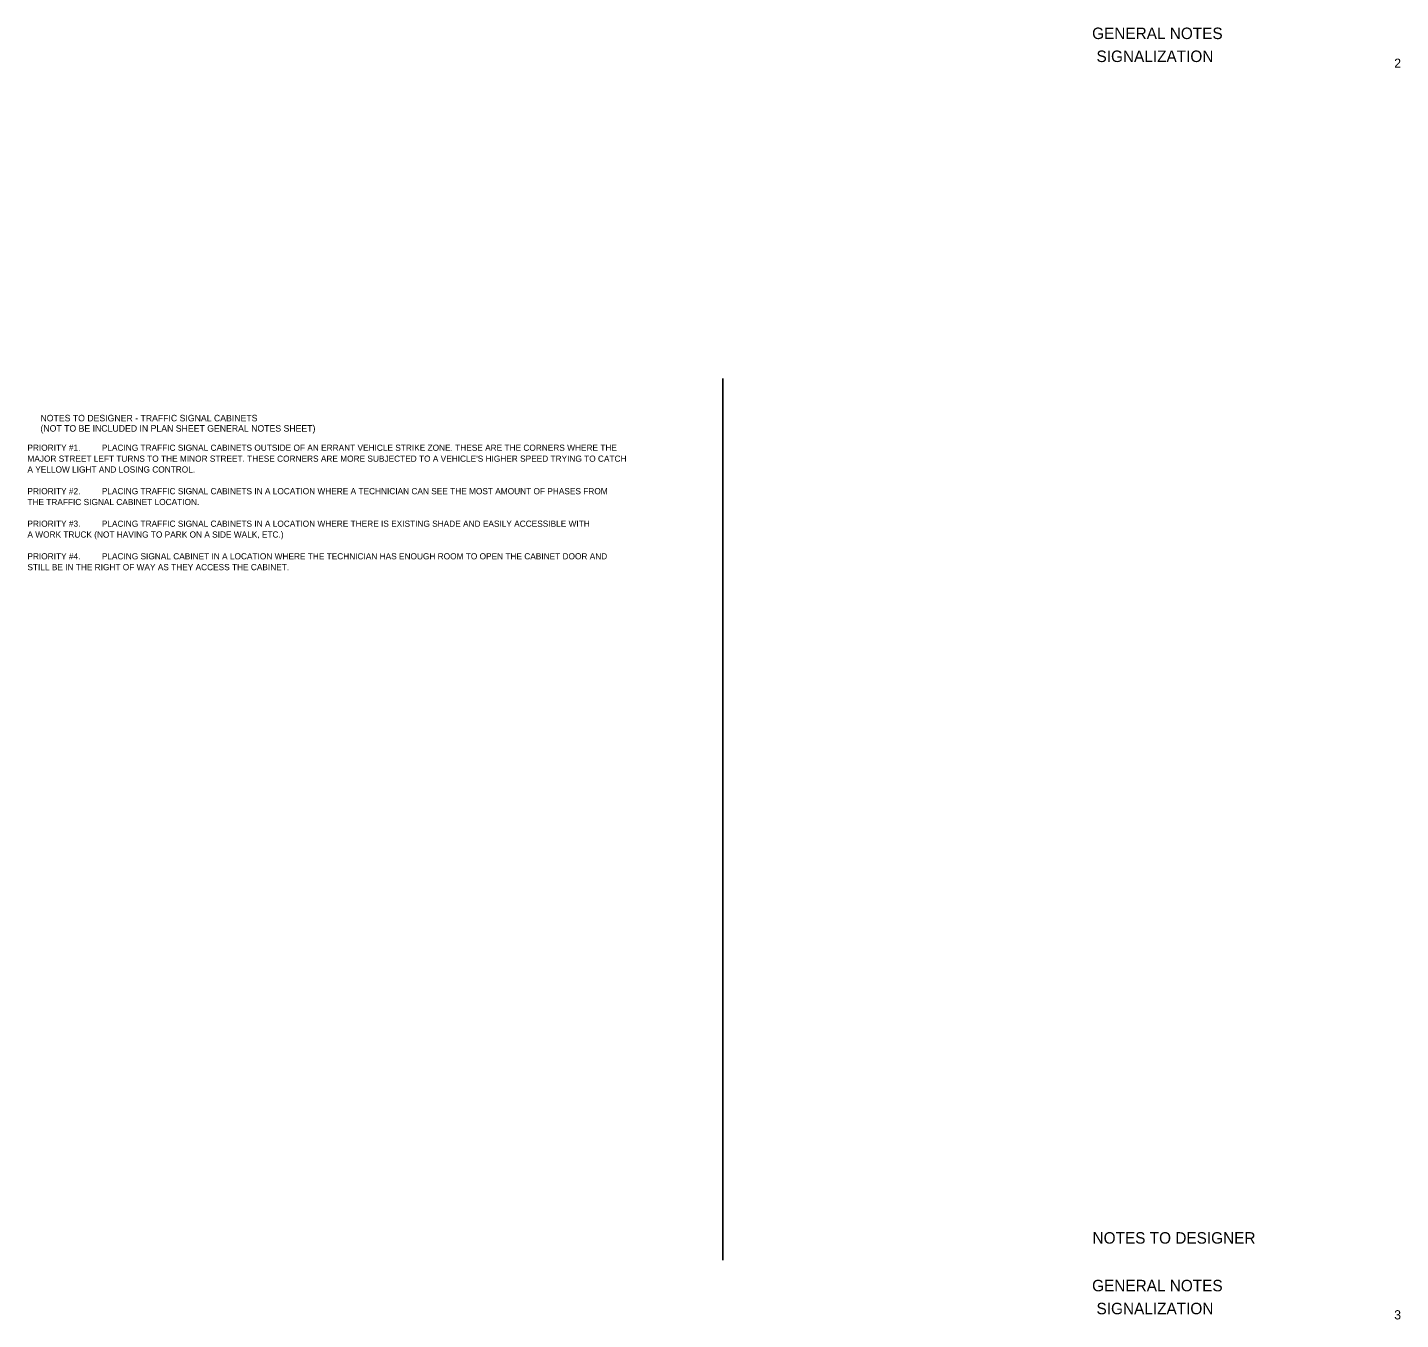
# Model space of a CAD drawing. Extents: x 2479946 to 2483081, y 3677527 to 3681234.
# Drawn here: x 2480014 to 2481509, y 3677527 to 3678934 of the extents above; entities that cross this region are included whole.
import ezdxf

# ---------------------------------------------------------------- set-up
doc = ezdxf.new("R2010")
doc.units = 0
for name, color, linetype in [('40', 7, 'Continuous'), ('ActivePointCell_dp', 7, 'Continuous'), ('RoadwayMisc', 7, 'Continuous'), ('TextMinor', 7, 'Continuous')]:
    doc.layers.add(name, color=color, linetype=linetype)

msp = doc.modelspace()

# ---------------------------------------------------------------- linework, layer by layer
at = {"layer": 'ActivePointCell_dp'}
msp.add_line((2480770.9, 3677591.5), (2480770.9, 3678551.5), dxfattribs=at)

# ---------------------------------------------------------------- texts
at = {"layer": '40'}
for s, height, p in [('NOTES TO DESIGNER - TRAFFIC SIGNAL CABINETS', 7.08, (2480028, 3678504.8)), ('(NOT TO BE INCLUDED IN PLAN SHEET GENERAL NOTES SHEET)', 7.08, (2480028, 3678493.6)), ('PRIORITY #1.', 6.75, (2480013.8, 3678472.7)), ('PLACING TRAFFIC SIGNAL CABINETS OUTSIDE OF AN ERRANT VEHICLE STRIKE ZONE. THESE ARE THE CORNERS WHERE THE ', 6.75, (2480094.8, 3678472.7)), ("MAJOR STREET LEFT TURNS TO THE MINOR STREET. THESE CORNERS ARE MORE SUBJECTED TO A VEHICLE'S HIGHER SPEED TRYING TO CATCH ", 6.75, (2480013.8, 3678460.8)), ('A YELLOW LIGHT AND LOSING CONTROL. ', 6.75, (2480013.8, 3678449)), ('PRIORITY #2.', 6.75, (2480013.8, 3678425.4)), ('PLACING TRAFFIC SIGNAL CABINETS IN A LOCATION WHERE A TECHNICIAN CAN SEE THE MOST AMOUNT OF PHASES FROM', 6.75, (2480094.8, 3678425.4)), ('THE TRAFFIC SIGNAL CABINET LOCATION.', 6.75, (2480013.8, 3678413.6)), ('A WORK TRUCK (NOT HAVING TO PARK ON A SIDE WALK, ETC.)', 6.75, (2480013.8, 3678378.2)), ('PRIORITY #3.', 6.75, (2480013.8, 3678390)), ('PLACING TRAFFIC SIGNAL CABINETS IN A LOCATION WHERE THERE IS EXISTING SHADE AND EASILY ACCESSIBLE WITH', 6.75, (2480094.8, 3678390)), ('PRIORITY #4.', 6.75, (2480013.8, 3678354.5)), ('PLACING SIGNAL CABINET IN A LOCATION WHERE THE TECHNICIAN HAS ENOUGH ROOM TO OPEN THE CABINET DOOR AND ', 6.75, (2480094.8, 3678354.5)), ('STILL BE IN THE RIGHT OF WAY AS THEY ACCESS THE CABINET. ', 6.75, (2480013.8, 3678342.7))]:
    msp.add_text(s, height=height, dxfattribs=at).set_placement(p)
at = {"layer": 'RoadwayMisc'}
for s, p in [('2', (2481501.7, 3678889.7)), ('3', (2481501.7, 3677527))]:
    msp.add_text(s, height=10, rotation=360, dxfattribs=at).set_placement(p)
at = {"layer": 'TextMinor'}
for s, p in [('     GENERAL NOTES      ', (2481149.6, 3678921)), ('     SIGNALIZATION      ', (2481154.4, 3678896)), ('NOTES TO DESIGNER', (2481173.3, 3677609.5)), ('     GENERAL NOTES      ', (2481149.6, 3677557.6)), ('     SIGNALIZATION      ', (2481154.4, 3677532.6))]:
    msp.add_text(s, height=12.5, rotation=360, dxfattribs=at).set_placement(p)

doc.saveas('drawing.dxf')
